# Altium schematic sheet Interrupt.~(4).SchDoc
size A; SheetNumber: 1; SheetTotal: 1
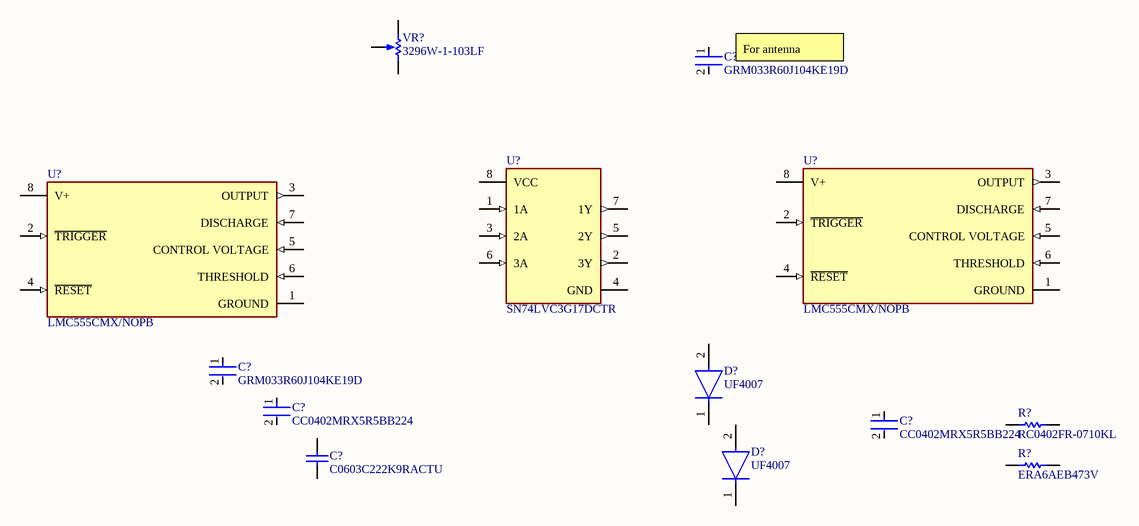
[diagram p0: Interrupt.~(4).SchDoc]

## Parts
(Parts that share a designator on the sheet are numbered #1, #2 ... from top to bottom, then left to right.)
C?#1  GRM033R60J104KE19D  [FP-GRM033-0_03-MFG]
C?#2  GRM033R60J104KE19D  [FP-GRM033-0_03-MFG]
C?#3  CC0402MRX5R5BB224  [FP-CC0402-MFG]
C?#4  CC0402MRX5R5BB224  [FP-CC0402-MFG]
C?#5  C0603C222K9RACTU  [CAPC1608X87X35LL15T15]
D?#1  UF4007  [FP-017AH-MFG]
D?#2  UF4007  [FP-017AH-MFG]
R?#1  RC0402FR-0710KL  [RESC1005X40X25LL05T10]
R?#2  ERA6AEB473V  [RESC2013X60X40LL20T25]
U?#1  SN74LVC3G17DCTR  [FP-DCT0008A-MFG]
U?#2  LMC555CMX/NOPB  [FP-D0008A-MFG]
U?#3  LMC555CMX/NOPB  [FP-D0008A-MFG]
VR?  3296W-1-103LF  [BOUR-3296W]

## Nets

Not connected (* = marked no-connect by the designer): C?#1 1 2; C?#2 1 2; C?#3 1 2; C?#4 1 2; C?#5 1 2; D?#1 1(C) 2(A); D?#2 1(C) 2(A); R?#1 1 2; R?#2 1 2; U?#1 1(1A) 2(3Y) 3(2A) 4(GND) 5(2Y) 6(3A) 7(1Y) 8(VCC); U?#2 1(GROUND) 2(~{TRIGGER}) 3(OUTPUT) 4(~{RESET}) 5(CONTROL_VOLTAGE) 6(THRESHOLD) 7(DISCHARGE) 8(V+); U?#3 1(GROUND) 2(~{TRIGGER}) 3(OUTPUT) 4(~{RESET}) 5(CONTROL_VOLTAGE) 6(THRESHOLD) 7(DISCHARGE) 8(V+); VR? 1(CCW) 2(S) 3(CW)

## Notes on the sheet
- (near C?#1) For antenna

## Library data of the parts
C?#1 = CMP-06035-000062-2: Chip Multilayer Ceramic Capacitors for General Purpose, 0201, 0.10uF, X5R, 15%, 10%, 6.3V; Capacitance: 100nF
C?#2 = CMP-06035-000062-2: 100 nF Chip Multilayer Ceramic Capacitors for General Purpose, 0201, 0.10uF, X5R, 15%, 10%, 6.3V; Capacitance: 100nF
C?#3 C?#4 = CMP-03422-000657-1: CAP CER 0.22UF 6.3V X5R 0402; Manufacturer: YAGEO; Automotive Grade: NA; Description: CC0402 220 nF X5R 20.00% 6.3 V; Material: Ceramic; Value: 220 nF; Tolerance: 0.2; Temperature Coefficient: 30ppm/°C
C?#5 = CMP-1035-02019-2: Manufacturer: Kemet
D?#1 D?#2 = CMP-2000-05028-2: DIODE GEN PURP 1KV 1A DO41; Manufacturer: ON Semiconductor; Capacitance: 17pF; Max Surge Forward Current: 30A; Description: Diode Standard 1000V 1A Through Hole DO-204AL (DO-41); Max Repetitive Reverse Voltage: 1000V; Value: 17pF; Max Junction Temp: +150°C; Peak Reverse Current: 10uA
R?#1 = CMP-2002-07353-1: Manufacturer: Yageo / Phycomp
R?#2 = CMP-2001-00645-1: Manufacturer: Panasonic
U?#1 = CMP-0859-00525-5: IC BUFFER NON-INVERT 5.5V SM8; Manufacturer: Texas Instruments; Logic Function Desc: Non-Inverting; Propagation Delay: 5.1ns; Number Of Inputs: 3; Description: Buffer, Non-Inverting 3 Element 1 Bit per Element Push-Pull Output SM8 (SSOP); Standoff Height: 0mm; Nominal Supply Current: 10uA; Min Supply Voltage: 1.65V
U?#2 U?#3 = CMP-04858-000001-1: IC OSC SINGLE TIMER 3MHZ 8-SOIC; Manufacturer: Texas Instruments; Description: 555 Type, Timer/Oscillator (Single) IC 3MHz 8-SOIC; Number Of Timers/Counters: 1; Max Supply Voltage: 15V; Standoff Height: 0.11mm; Propagation Delay: 100ns; Nominal Supply Current: 50-150uA; Min Supply Voltage: 1.5V
VR? = CMP-1747-00001-1: Square Trimpot(R) Trimming Potentiometer, 10 KOhm, +/- 10%, 0.5 W, -55 to 125 degC, 3-Pin THD, RoHS, Tube; Voltage Rating: 75 V; Resistance: 120 Ohm; Tolerance: 1%; Power Rating: 100 mW; Case\Package: 0603; Type (Resistor): Thick Film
